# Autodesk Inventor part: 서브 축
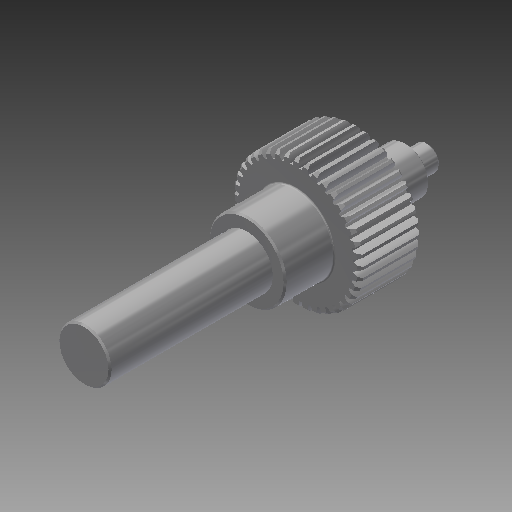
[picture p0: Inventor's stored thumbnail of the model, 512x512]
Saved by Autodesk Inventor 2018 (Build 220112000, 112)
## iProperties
Created: 2016-02
Part Number: 서브 축
Material: 강철, 연강
Document SubType Name: Modeling
Designer: mdu
Categories: <?xml version="1.0" encoding="UTF-16"?> <MemberInstance><Categories><FamilyTemplate><FamilyTemplateParameter ValueType="xs:double" Id="1" ObjectReferenceKey="da
Density: 7.86 g/cm^3
Appearance: 강철
CustomPartVersion: 1
Author: mdu
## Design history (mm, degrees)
sketch "Sketch1"
  geometry: C1 r 21 at (0, 0)
  constraints: 1 centre point
  dimensions: "d0" = 42 diameter of C1 (= da_da)
extrude "Extrusion1" new body sketch "Sketch1" distance "d1" = 20 (= da_b); taper "d2" = 0 deg
workplane "Work Plane2"
feature "피치 지름" dims "d4" = 10, "d5" = 0
workplane "Work Plane8"
workplane "Work Plane9"
chamfer "모따기1" distance "d49" = 1; stored, may be unused: second distance "d50" = 2, angle "d51" = 45 deg
sketch "스케치3"
  geometry: C1 r 12.5 at (0, 0); 1 further point
  constraints: 1 centre point, 1 coincident
  dimensions: "d52" = 25 diameter of C1
extrude "돌출2" join sketch "스케치3" distance "d53" = 16; taper "d54" = 0 deg
sketch "스케치4"
  geometry: C1 r 8.5 at (0, 0); 1 further point
  constraints: 1 centre point, 1 coincident
  dimensions: "d55" = 17 diameter of C1
extrude "돌출3" join sketch "스케치4" distance "d56" = 53; taper "d57" = 0 deg
sketch "스케치5"
  geometry: C1 r 7.5 at (0, 0); 1 further point
  constraints: 1 centre point, 1 coincident
  dimensions: "d62" = 15 diameter of C1
extrude "돌출4" join sketch "스케치5" distance "d63" = 16; taper "d64" = 0 deg
sketch "스케치6"
  geometry: C1 r 4 at (0, 0); 1 further point
  constraints: 1 centre point, 1 coincident
  dimensions: "d65" = 8 diameter of C1
extrude "돌출5" join sketch "스케치6" distance "d66" = 7; taper "d67" = 0 deg
chamfer "모따기2" distance "d58" = 0.5; stored, may be unused: second distance "d59" = 2, angle "d60" = 45 deg
fillet "모깎기1" dims "d61" = 0.5
feature "스퍼 기어" dims "d34" = 4.5 deg (computed from da_z), "da_b" = 20, "da_d" = 40, "da_aw" = 31, "da_da" = 42, "da_df" = 37.5, "da_dw" = 40, angle "da_beta" = 0 deg, "da_lefttooth" = 0, "da_righttooth" = 0
body "Solid1"
sketch "Sketch2"
  geometry: C1 r 21 at (0, 0) reference; C2 r 20 at (0, 0)
  constraints: 1 centre point, 1 coincident
  dimensions: "d3" = 40 diameter of C2 (= da_dw)
body "Srf1"
other parameters: "d16" = 31 (= da_aw), "d17" = 0, "d39" = 0, "d41" = 0, "d43" = 31 (= da_aw), "d46" = 31 (= da_aw), "d47" = 0, "d48" = 0
